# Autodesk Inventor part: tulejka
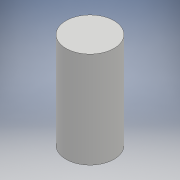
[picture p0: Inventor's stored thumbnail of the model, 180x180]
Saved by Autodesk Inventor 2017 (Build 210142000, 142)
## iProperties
Created: 2020-09
Part Number: tulejka
Material: Generic
Document SubType Name: Modeling
Designer: WindowsX
Density: 1 g/cm^3
Appearance: Default
Author: WindowsX
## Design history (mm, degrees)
sketch "Szkic1"
  geometry: C1 r 10 at (0, 0); 1 further point
  constraints: 1 centre point, 1 coincident
  dimensions: "d0" = 20 diameter of C1
extrude "Wyciągnięcie proste1" new body sketch "Szkic1" distance "d1" = 40; taper "d2" = 0 deg
node "Bryła1"
